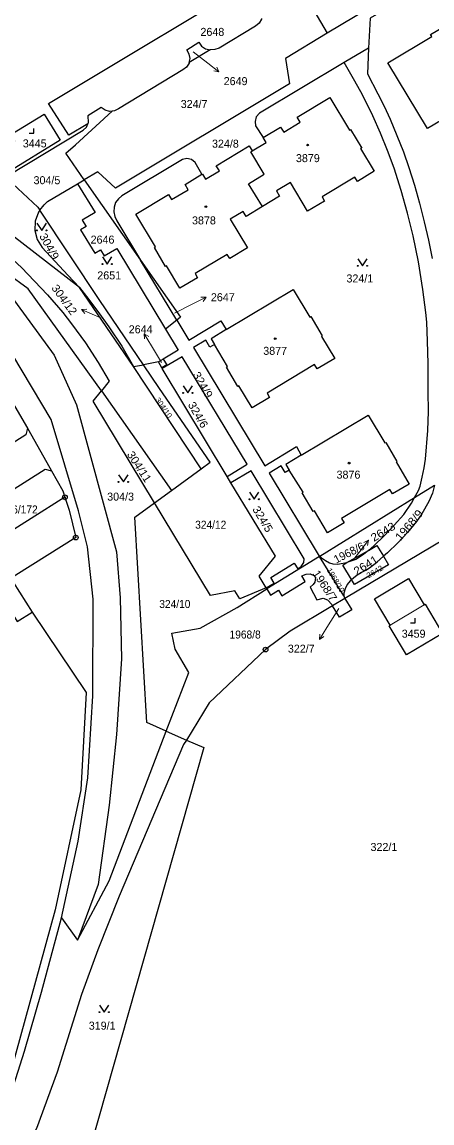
# Model space of a CAD drawing. Extents: x -679733 to -673243, y -1075091 to -1066557.
# Drawn here: x -676072.8 to -675985.8, y -1072574.2 to -1072340.3 of the extents above; entities that cross this region are included whole.
import ezdxf
from ezdxf.enums import TextEntityAlignment as Align

# ---------------------------------------------------------------- set-up
doc = ezdxf.new("R2010")
doc.units = 0
doc.header["$LTSCALE"] = 0.68
for name, color, linetype, lineweight in [('1', 7, 'Continuous', 25), ('3', 7, 'Continuous', 25), ('4', 7, 'Continuous', 13), ('5', 7, 'Continuous', 25), ('7', 7, 'Continuous', 13), ('8', 7, 'Continuous', 25)]:
    doc.layers.add(name, color=color, linetype=linetype, lineweight=lineweight)
doc.layers.add('2', color=7, linetype='Continuous')

msp = doc.modelspace()

# ---------------------------------------------------------------- linework, layer by layer
at = {"layer": '1'}
for p, q in [((-675999.25, -1072345.84), (-676004.46, -1072348.87)), ((-676061.07, -1072374.67), (-676059.59, -1072373.8)), ((-676059.59, -1072373.8), (-676047.65, -1072390.88)), ((-676039.95, -1072403.63), (-676047.65, -1072390.88)), ((-676039.95, -1072403.63), (-676042.34, -1072405.57)), ((-676043.87, -1072412.53), (-676047.06, -1072413.1)), ((-676042.83, -1072411.9), (-676043.87, -1072412.53)), ((-676074.81, -1072421.15), (-676071.68, -1072426.57)), ((-675989.49, -1072441.33), (-675985.23, -1072438.69)), ((-676063.71, -1072441.28), (-676079.61, -1072451.28)), ((-676044.69, -1072442.45), (-676041.09, -1072439.81)), ((-676009.57, -1072453.78), (-675989.49, -1072441.33)), ((-676009.97, -1072453.41), (-676009.69, -1072453.85)), ((-676020.83, -1072460.75), (-676021, -1072460.48)), ((-676004.29, -1072462.79), (-676006.88, -1072464.32)), ((-676042.19, -1072490.98), (-676037.93, -1072492.84)), ((-676064.43, -1072530.6), (-676061.06, -1072535.34))]:
    msp.add_line(p, q, dxfattribs=at)
for points in [[(-675978.49, -1072315.33), (-675999.37, -1072327.75), (-676004.57, -1072330.85), (-676008.08, -1072331.18), (-676013.03, -1072334.17), (-676008.07, -1072342.7)], [(-676060.65, -1072396.71), (-676088.94, -1072374.82), (-676097.4, -1072369.15), (-676135.11, -1072342.81), (-676158.9, -1072326.2), (-676174.82, -1072318.97)], [(-675974.15, -1072322.36), (-675983.94, -1072328.23), (-676008.07, -1072342.7)], [(-676058.87, -1072361.92), (-676062.91, -1072364.37), (-676067.19, -1072357.62), (-676018.56, -1072328.36)], [(-675972.06, -1072340.04), (-675971.62, -1072339.22), (-675971.71, -1072338.5), (-675976.37, -1072330.82), (-675977.05, -1072330.09), (-675977.86, -1072329.49), (-675978.74, -1072329.04), (-675979.71, -1072328.91), (-675980.69, -1072329.04), (-675981.59, -1072329.44), (-675998.93, -1072339.45), (-675999.25, -1072345.84)], [(-675973.65, -1072363.72), (-675977.43, -1072357.37), (-675986.75, -1072362.96), (-675995.15, -1072348.94), (-675985.86, -1072343.37), (-675986.09, -1072342.93), (-675983.36, -1072341.3), (-675983.11, -1072341.72), (-675974.24, -1072336.41), (-675972.06, -1072340.04)], [(-676021.95, -1072339.58), (-676021.99, -1072339.73), (-676022.47, -1072340.58), (-676023.26, -1072341.22), (-676030.96, -1072345.86), (-676031.91, -1072346.14), (-676032.91, -1072346.21), (-676037.32, -1072348.88)], [(-676008.07, -1072342.7), (-676016.9, -1072348.05), (-676016.06, -1072353.42), (-676052.99, -1072375.57), (-676056.75, -1072372.12), (-676059.59, -1072373.8)], [(-676037.32, -1072348.88), (-676037.12, -1072348.08), (-676037.31, -1072347.11), (-676037.8, -1072346.23), (-676035.25, -1072344.59), (-676034.69, -1072345.43), (-676033.88, -1072346.01), (-676032.91, -1072346.21)], [(-675999.25, -1072345.84), (-675999.49, -1072351.3), (-675997.27, -1072355.54), (-675995.97, -1072358.21), (-675994.69, -1072360.96), (-675991.87, -1072367.89), (-675990.7, -1072371.22), (-675989.51, -1072374.99), (-675988.44, -1072378.82), (-675987.43, -1072382.78), (-675986.55, -1072386.62), (-675985.72, -1072390.52)], [(-676037.32, -1072348.88), (-676037.36, -1072349.04), (-676037.89, -1072349.92), (-676038.66, -1072350.49), (-676052.34, -1072358.76), (-676053.22, -1072359.19), (-676053.69, -1072359.24)], [(-676004.46, -1072348.87), (-676022.41, -1072359.7), (-676023.08, -1072360.43), (-676023.33, -1072361.41), (-676023.27, -1072362.39), (-676021.62, -1072364.83)], [(-675989.49, -1072441.33), (-675988.69, -1072439.84), (-675988.33, -1072438.9), (-675987.87, -1072436.99), (-675987.46, -1072435.02), (-675987.15, -1072433.15), (-675986.64, -1072427.07), (-675986.54, -1072423.06), (-675986.59, -1072418.8), (-675986.61, -1072412.88), (-675986.73, -1072408.08), (-675986.89, -1072404.06), (-675987.08, -1072402.03), (-675987.71, -1072397.13), (-675988.67, -1072391.22), (-675989.82, -1072385.74), (-675991.01, -1072380.89), (-675992.36, -1072376.1), (-675993.84, -1072371.33), (-675995.21, -1072367.58), (-675996.7, -1072363.89), (-675998.34, -1072360.23), (-676000.56, -1072355.75), (-676002.15, -1072352.84), (-676004.46, -1072348.87)], [(-676021.62, -1072364.83), (-676017.92, -1072362.61), (-676017.27, -1072363.68), (-676013.79, -1072361.59), (-676014.43, -1072360.52), (-676007.45, -1072356.32), (-676003.3, -1072363.25), (-676003.08, -1072363.14), (-676000.72, -1072367.07), (-676000.94, -1072367.2), (-675998.08, -1072371.98), (-676001.59, -1072374.15), (-676002.14, -1072373.24), (-676009.13, -1072377.47), (-676008.59, -1072378.36), (-676012.2, -1072380.5), (-676015.82, -1072374.42), (-676018.78, -1072376.18), (-676018.14, -1072377.29), (-676021.8, -1072379.52)], [(-676076.81, -1072370.93), (-676078.49, -1072368.07), (-676074.37, -1072365.54), (-676075.2, -1072364.18), (-676068.11, -1072359.86), (-676064.71, -1072365.4), (-676075.98, -1072372.34)], [(-676059.59, -1072373.8), (-676063.5, -1072368.19), (-676061.5, -1072366.41), (-676053.69, -1072359.24)], [(-676053.69, -1072359.24), (-676054.22, -1072359.3), (-676055.16, -1072359.03), (-676056.01, -1072358.47), (-676058.86, -1072360.2), (-676058.78, -1072361.67), (-676058.87, -1072361.92)], [(-676075.92, -1072372.98), (-676059.85, -1072363.28), (-676059.12, -1072362.62), (-676058.87, -1072361.92)], [(-676064.43, -1072530.6), (-676060.93, -1072514.33), (-676058.84, -1072500.85), (-676057.79, -1072483.42), (-676057.73, -1072462.91), (-676058.94, -1072451.8), (-676060.84, -1072444.17), (-676066.6, -1072424.75), (-676080.98, -1072400.72), (-676089.25, -1072390.86), (-676096.74, -1072383.24), (-676106.51, -1072374.56), (-676118.43, -1072364.57)], [(-676117.22, -1072363.74), (-676116.34, -1072363.6), (-676089.85, -1072379.52), (-676087.32, -1072381.13), (-676082.85, -1072384.09), (-676077.34, -1072388.44), (-676072.91, -1072392.49), (-676067.41, -1072398.29), (-676064.13, -1072402.03), (-676062.28, -1072404.41), (-676059.34, -1072408.48), (-676056.62, -1072412.67), (-676054.33, -1072416.58), (-676055.95, -1072418.63)], [(-676034.62, -1072372.65), (-676034.53, -1072372.6), (-676033.88, -1072373.68), (-676030.93, -1072371.91), (-676031.58, -1072370.83), (-676024.57, -1072366.61), (-676023.93, -1072367.7)], [(-676023.93, -1072367.7), (-676020.97, -1072365.92), (-676021.62, -1072364.83)], [(-676034.62, -1072372.65), (-676036.08, -1072370.15), (-676036.84, -1072369.52), (-676037.82, -1072369.28), (-676038.77, -1072369.53), (-676051.6, -1072377.25), (-676052.37, -1072377.88), (-676052.95, -1072378.68), (-676053.27, -1072379.63), (-676053.36, -1072380.63), (-676053.13, -1072381.6), (-676052.71, -1072382.51), (-676047.65, -1072390.88)], [(-676021.8, -1072379.52), (-676024.74, -1072374.65), (-676021.41, -1072372.65), (-676024.27, -1072367.91), (-676023.93, -1072367.7)], [(-676075.92, -1072372.98), (-676075.86, -1072373.72), (-676069.43, -1072379.63), (-676069.02, -1072380.25)], [(-676021.8, -1072379.52), (-676025.23, -1072381.6), (-676025.85, -1072380.54), (-676028.64, -1072382.18), (-676024.97, -1072388.29), (-676028.73, -1072390.55), (-676029.26, -1072389.67), (-676036.07, -1072393.76), (-676035.56, -1072394.68), (-676039.31, -1072396.88), (-676042.14, -1072392.11), (-676042.36, -1072392.24), (-676044.71, -1072388.2), (-676044.49, -1072388.07), (-676048.65, -1072381.11), (-676041.7, -1072376.92), (-676041.06, -1072378), (-676037.56, -1072375.92), (-676038.21, -1072374.82), (-676034.62, -1072372.65)], [(-676069.02, -1072380.25), (-676068.14, -1072379.11), (-676067.39, -1072378.45), (-676061.07, -1072374.67)], [(-676061.07, -1072374.67), (-676057.31, -1072380.74), (-676060.03, -1072382.41), (-676059.17, -1072383.71), (-676060.38, -1072384.42), (-676057.36, -1072389.39), (-676056.15, -1072388.68), (-676055.41, -1072390.01), (-676052.69, -1072388.41), (-676042.34, -1072405.57)], [(-676069.02, -1072380.25), (-676069.35, -1072380.69), (-676070, -1072382.58), (-676070.09, -1072384.61), (-676069.58, -1072386.51), (-676068.57, -1072388.23), (-676063.1, -1072394.07), (-676060.65, -1072396.71)], [(-676047.06, -1072413.1), (-676056.32, -1072399.44), (-676069.02, -1072380.25)], [(-676055.95, -1072418.63), (-676071.52, -1072396.99), (-676084.95, -1072387.22)], [(-676084.95, -1072387.22), (-676077.08, -1072395.86), (-676065.96, -1072411.11), (-676061.23, -1072421.61), (-676052.78, -1072452.85), (-676052.01, -1072462.63), (-676051.68, -1072475.56), (-676052.77, -1072491.68), (-676054.32, -1072506.68), (-676056.64, -1072523.56), (-676061.06, -1072535.34)], [(-676047.65, -1072390.88), (-676039.18, -1072403.01), (-676039.95, -1072403.63)], [(-676060.65, -1072396.71), (-676059.15, -1072398.6), (-676056.74, -1072401.78), (-676054.39, -1072405.09), (-676051.66, -1072409.2), (-676049.15, -1072413.47), (-676047.06, -1072413.1)], [(-676055.95, -1072418.63), (-676041.09, -1072439.81), (-676034.81, -1072435.22), (-676049.15, -1072413.47), (-676060.65, -1072396.71)], [(-676029.48, -1072405.65), (-676015.26, -1072397.11), (-676011.74, -1072402.99), (-676011.52, -1072402.86), (-676009.07, -1072406.95), (-676009.26, -1072407.09), (-676006.45, -1072411.79), (-676010.17, -1072413.98), (-676010.74, -1072413.04), (-676020.8, -1072419.12), (-676020.27, -1072420.06), (-676023.94, -1072422.26), (-676026.77, -1072417.58), (-676026.99, -1072417.71), (-676029.44, -1072413.61), (-676029.22, -1072413.46), (-676031.99, -1072408.78)], [(-676039.95, -1072403.63), (-676037.39, -1072407.87), (-676030.58, -1072403.81), (-676029.48, -1072405.65)], [(-676042.34, -1072405.57), (-676039.68, -1072409.99), (-676042.83, -1072411.9)], [(-676029.48, -1072405.65), (-676032.7, -1072407.58), (-676031.99, -1072408.78)], [(-676031.99, -1072408.78), (-676032.95, -1072409.36), (-676033.8, -1072407.91), (-676036.45, -1072409.48), (-676021.27, -1072434.57), (-676014.57, -1072430.49), (-676013.55, -1072432.35)], [(-676029.28, -1072436.87), (-676025.03, -1072434.22), (-676038.81, -1072411.43), (-676043.04, -1072413.92)], [(-676034.81, -1072435.22), (-676032.9, -1072433.82), (-676043.62, -1072418.17), (-676047.06, -1072413.1)], [(-676021, -1072460.48), (-676022.47, -1072458.01), (-676018.99, -1072453.8), (-676028.47, -1072438.22), (-676029.28, -1072436.87), (-676043.04, -1072413.92), (-676043.12, -1072413.79), (-676043.87, -1072412.53)], [(-676042.83, -1072411.9), (-676042.07, -1072413.15), (-676043.12, -1072413.79)], [(-675925.21, -1072415.73), (-675969.92, -1072442.3), (-676004.29, -1072462.79)], [(-676044.69, -1072442.45), (-676057.69, -1072420.83), (-676055.95, -1072418.63)], [(-676013.55, -1072432.35), (-675999.35, -1072423.86), (-675995.8, -1072429.72), (-675995.6, -1072429.64), (-675993.24, -1072433.66), (-675993.43, -1072433.73), (-675990.62, -1072438.48), (-675994.17, -1072440.55), (-675994.74, -1072439.6), (-676004.99, -1072445.75), (-676004.42, -1072446.69), (-676007.99, -1072448.85), (-676010.76, -1072444.17), (-676010.98, -1072444.3), (-676013.38, -1072440.31), (-676013.17, -1072440.18), (-676016.11, -1072435.5)], [(-676071.68, -1072426.57), (-676072.03, -1072427.97), (-676087.9, -1072438.04)], [(-676071.68, -1072426.57), (-676070.73, -1072428.23), (-676066.53, -1072435.67)], [(-676013.55, -1072432.35), (-676016.85, -1072434.32), (-676016.11, -1072435.5)], [(-676016.11, -1072435.5), (-676016.99, -1072436.01), (-676017.81, -1072434.62), (-676020.32, -1072436.14), (-676009.97, -1072453.41), (-676009.57, -1072453.78)], [(-676083.47, -1072445.14), (-676067.87, -1072435.33), (-676066.53, -1072435.67)], [(-676066.53, -1072435.67), (-676064.15, -1072439.9), (-676063.71, -1072441.28)], [(-676021, -1072460.48), (-676019.28, -1072459.53), (-676020, -1072458.34), (-676015.02, -1072455.3), (-676014.29, -1072456.49), (-676013.53, -1072455.96), (-676013.02, -1072455.12), (-676012.93, -1072454.35), (-676024.17, -1072435.66), (-676028.47, -1072438.22)], [(-675985.23, -1072438.69), (-675985.69, -1072440.4), (-675986.43, -1072442.18), (-675987.95, -1072444.81), (-675989.1, -1072446.43), (-675991.01, -1072448.73), (-675993.07, -1072450.95), (-675995.23, -1072453.04), (-675996.08, -1072453.79)], [(-676063.71, -1072441.28), (-676062.84, -1072444.02), (-676061.41, -1072449.82), (-676145.85, -1072502.88), (-676156.45, -1072486.01)], [(-675999.3, -1072452.56), (-675998.13, -1072451.59), (-675995.84, -1072449.37), (-675993.8, -1072447.23), (-675991.78, -1072444.95), (-675990.11, -1072442.49), (-675989.49, -1072441.33)], [(-676042.19, -1072490.98), (-676046.35, -1072489.15), (-676048.88, -1072445.51), (-676044.69, -1072442.45)], [(-676021, -1072460.48), (-676026.56, -1072462.81), (-676027.61, -1072461.18), (-676032.84, -1072462.17), (-676044.69, -1072442.45)], [(-676009.57, -1072453.78), (-676009.22, -1072454.1), (-676008.43, -1072454.68), (-676007.54, -1072455.17), (-676006.83, -1072455.4), (-676005.85, -1072455.46), (-676003.88, -1072455.15), (-675999.3, -1072452.56)], [(-675999.3, -1072452.56), (-676000.3, -1072453.4), (-676001.97, -1072454.47), (-676003.88, -1072455.15)], [(-675999.3, -1072452.56), (-675997.47, -1072451.5), (-675996.08, -1072453.79)], [(-676004.52, -1072462.18), (-676009.69, -1072453.85), (-676020.83, -1072460.75)], [(-676002.88, -1072458.76), (-676004.73, -1072455.68), (-676003.88, -1072455.15)], [(-675996.08, -1072453.79), (-675995.05, -1072455.59), (-676002.26, -1072459.82), (-676002.88, -1072458.76)], [(-676002.88, -1072458.76), (-676002.46, -1072458.35), (-676001.67, -1072457.74), (-676000.83, -1072457.23), (-675999.87, -1072456.74), (-675999.09, -1072456.25), (-675997.5, -1072455.04), (-675996.08, -1072453.79)], [(-676020.83, -1072460.75), (-676020.04, -1072462.04), (-676018.39, -1072460.99), (-676017.68, -1072462.18), (-676012.68, -1072459.15), (-676013.39, -1072457.96), (-676012.53, -1072457.58), (-676011.64, -1072457.55), (-676010.84, -1072457.91), (-676010.53, -1072458.33), (-676010.67, -1072459.3), (-676011.05, -1072459.8), (-676011.64, -1072460.34), (-676010.23, -1072463.09), (-676008.89, -1072462.7), (-676007.94, -1072463.03), (-676006.99, -1072464.14), (-676006.88, -1072464.32)], [(-676077.85, -1072461.24), (-676074.72, -1072459.27), (-676070.69, -1072465.69)], [(-676002.88, -1072458.76), (-676003.16, -1072459.03), (-676003.78, -1072459.83), (-676004.24, -1072460.72), (-676004.49, -1072461.67), (-676004.52, -1072462.18)], [(-676077.85, -1072461.24), (-676073.86, -1072467.68), (-676070.69, -1072465.69)], [(-676042.19, -1072490.98), (-676037.42, -1072478.47), (-676040.3, -1072473.56), (-676041.01, -1072470.17), (-676035.02, -1072469.05), (-676027.15, -1072464.67), (-676020.83, -1072460.75)], [(-676004.29, -1072462.79), (-676002.82, -1072465.18), (-676005.42, -1072466.71), (-676006.88, -1072464.32)], [(-676004.52, -1072462.18), (-676004.39, -1072462.63), (-676004.29, -1072462.79)], [(-676006.88, -1072464.32), (-676015.88, -1072469.69), (-676021.11, -1072473.62), (-676033.07, -1072484.95), (-676037.93, -1072492.84)], [(-676070.69, -1072465.69), (-676059.17, -1072482.71), (-676060.35, -1072503.43), (-676065.77, -1072528.95), (-676076.34, -1072567.38), (-676083.41, -1072584.95), (-676093.32, -1072601.73), (-676100.75, -1072617.65), (-676109.37, -1072640.15)], [(-676061.06, -1072535.34), (-676054.3, -1072522.75), (-676042.19, -1072490.98)], [(-676037.93, -1072492.84), (-676038.52, -1072493.79), (-676052.18, -1072525.99), (-676056.74, -1072537.42), (-676060.22, -1072546.9), (-676065.36, -1072563.37), (-676069.71, -1072575.38), (-676077.66, -1072589.53), (-676083.71, -1072599.1)], [(-676037.93, -1072492.84), (-676034.24, -1072494.46), (-676064.58, -1072601.42), (-676045.67, -1072631.18)], [(-676108.14, -1072640.63), (-676099.22, -1072618.24), (-676096.23, -1072611.41), (-676092.66, -1072604.31), (-676081.65, -1072584.47), (-676079.59, -1072580.02), (-676075.54, -1072569.2), (-676072.31, -1072558.92), (-676068.71, -1072546.39), (-676064.43, -1072530.6)]]:
    msp.add_lwpolyline(points, dxfattribs=at)
msp.add_lwpolyline([(-675991.2, -1072474.75), (-675994.88, -1072468.56), (-675994.68, -1072468.44), (-675998.01, -1072462.83), (-675990.79, -1072458.55), (-675987.45, -1072464.1), (-675987.26, -1072463.96), (-675983.55, -1072470.21)], close=True, dxfattribs=at)
at = {"layer": '3'}
for points in [[(-676071.321, -1072363.9), (-676070.32, -1072363.9), (-676070.32, -1072362.9)], [(-676069.64, -1072383.059), (-676068.64, -1072384.56), (-676067.64, -1072383.059)], [(-676055.73, -1072390.219), (-676054.73, -1072391.72), (-676053.73, -1072390.219)], [(-676001.55, -1072390.599), (-676000.55, -1072392.1), (-675999.55, -1072390.599)], [(-676038.62, -1072417.599), (-676037.62, -1072419.1), (-676036.62, -1072417.599)], [(-676052.31, -1072436.519), (-676051.31, -1072438.02), (-676050.31, -1072436.519)], [(-676024.53, -1072440.189), (-676023.53, -1072441.69), (-676022.53, -1072440.189)], [(-675990.361, -1072467.94), (-675989.36, -1072467.94), (-675989.36, -1072466.94)], [(-676056.38, -1072549.149), (-676055.38, -1072550.65), (-676054.38, -1072549.149)]]:
    msp.add_lwpolyline(points, dxfattribs=at)
for centre in [(-676069.64, -1072384.5595), (-676067.64, -1072384.5595), (-676055.73, -1072391.7195), (-676053.73, -1072391.7195), (-676001.55, -1072392.0995), (-675999.55, -1072392.0995), (-676038.62, -1072419.0995), (-676036.62, -1072419.0995), (-676052.31, -1072438.0195), (-676050.31, -1072438.0195), (-676024.53, -1072441.6895), (-676022.53, -1072441.6895), (-676056.38, -1072550.6495), (-676054.38, -1072550.6495)]:
    msp.add_circle(centre, 0.1, dxfattribs=at)
at = {"layer": '4'}
msp.add_line((-675994.68, -1072468.44), (-675987.45, -1072464.1), dxfattribs=at)
at = {"layer": '5'}
for centre in [(-676012.1968, -1072366.4392), (-676033.7968, -1072379.5192), (-676019.0768, -1072407.5592), (-676003.3868, -1072434.0192)]:
    msp.add_circle(centre, 0.175, dxfattribs=at)
at = {"layer": '7'}
for p, q in [((-676031.015, -1072350.888), (-676031.496, -1072349.876)), ((-676033.726, -1072398.758), (-676034.846, -1072398.766)), ((-676060.162, -1072401.349), (-676059.45, -1072402.214)), ((-676046.876, -1072406.528), (-676046.789, -1072407.644)), ((-675999.262, -1072450.415), (-676000.274, -1072450.896)), ((-676009.7, -1072471.455), (-676008.745, -1072470.871))]:
    msp.add_line(p, q, dxfattribs=at)
for points in [[(-676036.49, -1072346.64), (-676033.38, -1072349.04), (-676031.015, -1072350.888), (-676032.113, -1072350.666)], [(-676040.42, -1072402.16), (-676036.4, -1072400.12), (-676033.726, -1072398.758), (-676034.391, -1072399.658)], [(-676056.13, -1072403.14), (-676057.42, -1072402.57), (-676060.162, -1072401.349), (-676059.043, -1072401.299)], [(-676043.24, -1072412.63), (-676045.33, -1072409.1), (-676046.876, -1072406.528), (-676045.931, -1072407.128)], [(-676002.46, -1072454.52), (-676001.11, -1072452.78), (-675999.262, -1072450.415), (-675999.484, -1072451.513)], [(-676005.59, -1072464.9), (-676008.11, -1072468.91), (-676009.7, -1072471.455), (-676009.594, -1072470.34)]]:
    msp.add_lwpolyline(points, dxfattribs=at)
at = {"layer": '8'}
for centre, radius in [((-676063.71, -1072441.2799), 0.5), ((-676063.71, -1072441.2799), 0.0303), ((-676061.41, -1072449.8199), 0.5), ((-676061.41, -1072449.8199), 0.0303), ((-676021.11, -1072473.6199), 0.5), ((-676021.11, -1072473.6199), 0.0303)]:
    msp.add_circle(centre, radius, dxfattribs=at)

# ---------------------------------------------------------------- texts
at = {"layer": '2'}
for s, p in [('2648', (-676034.94, -1072343.249)), ('2649', (-676030.01, -1072353.713)), ('324/7', (-676039.13, -1072358.57)), ('3445', (-676072.65, -1072366.94)), ('324/8', (-676032.49, -1072366.999)), ('3879', (-676014.67, -1072370.07)), ('304/5', (-676070.37, -1072374.759)), ('3878', (-676036.73, -1072383.3)), ('2646', (-676058.26, -1072387.38)), ('2651', (-676056.84, -1072394.979)), ('324/1', (-676003.95, -1072395.63)), ('2647', (-676032.72, -1072399.62)), ('3877', (-676021.61, -1072411.009)), ('3876', (-676006.05, -1072437.31)), ('304/3', (-676054.74, -1072441.979)), ('3459', (-675992.22, -1072471.1)), ('322/1', (-675998.84, -1072516.41)), ('319/1', (-676058.65, -1072554.37))]:
    msp.add_text(s, height=1.7, dxfattribs=at).set_placement(p)
for s, height, rotation, width, p in [('304/9', 1.7, 299, 1.05, (-676069.213, -1072385.772)), ('324/9', 1.7, 300, 1.05, (-676036.666, -1072415.235)), ('304/10', 1.14, 305, 1.05, (-676044.606, -1072420.576)), ('324/6', 1.7, 300, 1.05, (-676037.676, -1072421.594)), ('304/11', 1.7, 303, 1.05, (-676050.632, -1072432.162)), ('324/5', 1.7, 301, 1.05, (-676023.988, -1072443.787)), ('1968/9', 1.7, 50, 1.1, (-675992.478, -1072450.646)), ('2643', 1.7, 31, 1.1, (-675998.142, -1072450.778)), ('2641', 1.7, 32, 1.1, (-676001.769, -1072457.89)), ('2642', 1.14, 30, 1.1, (-675999.275, -1072458.493)), ('1968/7', 1.7, 303, 1.05, (-676011.232, -1072457.452))]:
    msp.add_text(s, height=height, rotation=rotation, dxfattribs=dict(at, width=width)).set_placement(p)
at = {"layer": '2', "width": 1.05}
msp.add_text('304/12', height=1.7, rotation=306, dxfattribs=at).set_placement((-676062.3723, -1072402.7358), align=Align.RIGHT)
at = {"layer": '2'}
for s, p in [('2644', (-676045.11, -1072406.43)), ('322/7', (-676010.699, -1072474.283))]:
    msp.add_text(s, height=1.7, dxfattribs=at).set_placement(p, align=Align.RIGHT)
at = {"layer": '2', "width": 0.95}
for s, p in [('306/172', (-676077.3, -1072444.71)), ('324/12', (-676036.06, -1072447.95)), ('324/10', (-676043.68, -1072464.79)), ('1968/8', (-676028.76, -1072471.279))]:
    msp.add_text(s, height=1.7, dxfattribs=at).set_placement(p)
at = {"layer": '2'}
for s, height, rotation, p in [('1968/6', 1.7, 27, (-676006.114, -1072455.367)), ('1968/10', 1.14, 301, (-676008.178, -1072456.753))]:
    msp.add_text(s, height=height, rotation=rotation, dxfattribs=at).set_placement(p)

doc.saveas('drawing.dxf')
